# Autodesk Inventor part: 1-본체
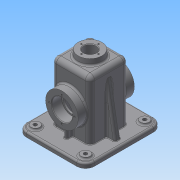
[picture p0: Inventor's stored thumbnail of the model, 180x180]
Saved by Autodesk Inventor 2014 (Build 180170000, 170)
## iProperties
Created: 2015-12
Part Number: 1-본체
Material: Generic
Document SubType Name: Modeling
Designer: Administrator
Density: 1 g/cm^3
Appearance: Default
Author: Administrator
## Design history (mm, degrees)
sketch "스케치1"
  geometry: L1 (-32.5, 32.5)-(32.5, 32.5); L2 (32.5, 32.5)-(32.5, -32.5); L3 (32.5, -32.5)-(-32.5, -32.5); L4 (-32.5, -32.5)-(-32.5, 32.5); L5 (-32.5, 32.5)-(32.5, -32.5); L6 (32.5, 32.5)-(-32.5, -32.5); 1 further point
  constraints: 12 end point, 2 midpoint, 2 parallel, 1 horizontal, 1 perpendicular
  dimensions: "d0" = 65 distance of L2.end L3.end; "d1" = 65 distance of L1.end L2.end
extrude "돌출1" new body sketch "스케치1" distance "d2" = 55; taper "d4" = 0 deg; dims "d3" = 55, "d5" = 0
feature "쉘1" dims "d6" = 5
node "작업 평면1"
sketch "스케치2"
  geometry: C1 r 20 at (0, 0); 1 further point
  constraints: 1 centre point, 1 coincident
  dimensions: "d8" = 40 diameter of C1
extrude "돌출2" join sketch "스케치2" stored distance "d9" = 55; taper "d10" = 5 deg
sketch "스케치3"
  geometry: C1 r 20 at (0, 0) reference; C2 r 10.5 at (0, 0)
  constraints: 1 centre point, 1 coincident
  dimensions: "d11" = 21 diameter of C2
extrude "돌출3" cut sketch "스케치3" stored distance "d12" = 55; taper "d13" = 0 deg
sketch "스케치4" dims "d14" = 29
  geometry: C1 r 20 at (0, 0) reference; 2 further points
  constraints: 1 coincident, 1 vertical alignment, 2 other
hole "구멍1" sketch "스케치4" at (0, 14.5) diameter "d15" = 2.459; stored, may be unused: countersink angle "d19" = 90 deg, drill point angle "d21" = 118 deg; dims "d16" = 7, "d17" = 4, "d18" = 2, "d20" = 9
sketch "스케치5"
  geometry: C1 r 27.5 at (32.5, -55); 1 further point
  constraints: 1 centre point, 1 coincident
  dimensions: "d25" = 55 diameter of C1
extrude "돌출4" join sketch "스케치5" distance "d26" = 15; taper "d27" = 0 deg
sketch "스케치6"
  geometry: C1 r 27.5 at (0, 0) reference; C2 r 17.5 at (0, 0)
  constraints: 1 centre point, 1 coincident
  dimensions: "d28" = 35 diameter of C2
extrude "돌출5" cut sketch "스케치6" distance "d29" = 17; taper "d30" = 0 deg
sketch "스케치7"
  geometry: C1 r 17.5 at (0, 0) reference; C2 r 15 at (0, 0)
  constraints: 1 centre point, 1 coincident
  dimensions: "d31" = 30 diameter of C2
extrude "돌출6" cut sketch "스케치7" distance "d32" = 3; taper "d33" = 0 deg
sketch "스케치8" dims "d34" = 42
  geometry: C1 r 27.5 at (0, 0) reference; 2 further points
  constraints: 1 coincident, 1 vertical alignment, 2 other
hole "구멍2" sketch "스케치8" at (0, 21) diameter "d35" = 3.242; stored, may be unused: countersink angle "d39" = 90 deg, drill point angle "d41" = 118 deg; dims "d36" = 8, "d37" = 4, "d38" = 2, "d40" = 10
sketch "스케치9"
  geometry: L1 (32.5, 32.5)-(-32.5, 32.5) reference; L2 (-32.5, 32.5)-(-32.5, -32.5) reference; L3 (-32.5, -32.5)-(32.5, -32.5) reference; L4 (32.5, -32.5)-(32.5, 32.5) reference; L5 (-42.5, -60)-(42.5, -60); L6 (52.5, -50)-(52.5, 50); L7 (42.5, 60)-(-42.5, 60); L8 (-52.5, 50)-(-52.5, -50); L9 (-52.5, -60)-(52.5, 60); L10 (52.5, -60)-(-52.5, 60); A1 r 10 centre (-42.5, -50) between (-52.5, -50) and (-42.5, -60); A2 r 10 centre (42.5, -50) between (42.5, -60) and (52.5, -50); A3 r 10 centre (42.5, 50) between (52.5, 50) and (42.5, 60); A4 r 10 centre (-42.5, 50) between (-42.5, 60) and (-52.5, 50); 1 further point
  constraints: 12 end point, 8 point on circle, 8 point on line, 8 tangent, 4 centre point, 3 equal radius, 2 midpoint, 2 parallel, 1 horizontal, 1 perpendicular
  dimensions: "d45" = 105 distance of L10.end L9.end; "d46" = 120 distance of L9.end L10.start; "d47" = 10 radius of A1
extrude "돌출7" join sketch "스케치9" distance "d48" = 2; taper "d49" = 0 deg
sketch "스케치10"
  geometry: L1 (32.5, -32.5)-(32.5, 32.5) reference; L2 (-32.5, -32.5)-(32.5, -32.5) reference; L3 (-32.5, 32.5)-(-32.5, -32.5) reference; L4 (32.5, 32.5)-(-32.5, 32.5) reference; L5 (42.5, -65)-(-42.5, -65); L6 (-57.5, -50)-(-57.5, 50); L7 (-42.5, 65)-(42.5, 65); L8 (57.5, 50)-(57.5, -50); L9 (57.5, -65)-(-57.5, 65); L10 (-57.5, -65)-(57.5, 65); A1 r 15 centre (42.5, -50) between (42.5, -65) and (57.5, -50); A2 r 15 centre (-42.5, -50) between (-57.5, -50) and (-42.5, -65); A3 r 15 centre (-42.5, 50) between (-42.5, 65) and (-57.5, 50); A4 r 15 centre (42.5, 50) between (57.5, 50) and (42.5, 65); 1 further point
  constraints: 12 end point, 8 point on circle, 8 point on line, 8 tangent, 4 centre point, 2 midpoint, 2 parallel, 1 horizontal, 1 perpendicular
  dimensions: "d50" = 115 distance of L9.end L10.end; "d51" = 130 distance of L10.start L9.end; "d52" = 15 radius of A1; "d53" = 15 radius of A2; "d54" = 15 radius of A3; "d55" = 15 radius of A4
extrude "돌출8" join sketch "스케치10" distance "d56" = 8; taper "d57" = 0 deg
sketch "스케치11"
  geometry: C1 r 3 at (-42.5, -50); C2 r 3 at (-42.5, 50); C3 r 3 at (42.5, 50); C4 r 3 at (42.5, -50); A1 r 10 centre (42.5, -50) between (42.5, -60) and (52.5, -50) reference; A2 r 10 centre (42.5, 50) between (52.5, 50) and (42.5, 60) reference; A3 r 10 centre (-42.5, 50) between (-42.5, 60) and (-52.5, 50) reference; A4 r 10 centre (-42.5, -50) between (-52.5, -50) and (-42.5, -60) reference; 1 further point
  constraints: 4 centre point, 4 coincident
  dimensions: "d58" = 6 diameter of C1; "d59" = 6 diameter of C2; "d60" = 6 diameter of C3; "d61" = 6 diameter of C4
extrude "돌출9" cut sketch "스케치11" distance "d62" = 10; taper "d63" = 0 deg
sketch "스케치12"
  geometry: C1 r 3 at (-42.5, 50) reference; C2 r 3 at (42.5, -50) reference; C3 r 3 at (42.5, 50) reference; C4 r 3 at (-42.5, -50) reference; C5 r 7.5 at (-42.5, -50); C6 r 7.5 at (-42.5, 50); C7 r 7.5 at (42.5, 50); C8 r 7.5 at (42.5, -50); A1 r 15 centre (42.5, -50) between (42.5, -65) and (57.5, -50) reference; A2 r 15 centre (42.5, 50) between (57.5, 50) and (42.5, 65) reference; A3 r 15 centre (-42.5, 50) between (-42.5, 65) and (-57.5, 50) reference; A4 r 15 centre (-42.5, -50) between (-57.5, -50) and (-42.5, -65) reference; 1 further point
  constraints: 4 centre point, 3 concentric, 1 coincident
  dimensions: "d64" = 15 diameter of C5; "d65" = 15 diameter of C6; "d66" = 15 diameter of C7; "d67" = 15 diameter of C8
extrude "돌출10" join sketch "스케치12" distance "d68" = 3; taper "d69" = 0 deg
sketch "스케치14"
  geometry: L1 (-27.5, 50)-(-27.5, -55) reference; L2 (-27.5, -55)-(-52.5, -55) reference; L3 (-52.5, -55)-(-52.5, -53) reference; L4 (-52.5, -53)-(-57.5, -53) reference; L5 (-57.5, -53)-(-57.5, -45) reference; L6 (-57.5, -45)-(-32.5, -45) reference; L7 (-32.5, -45)-(-32.5, 55) reference; L8 (-32.5, 55)-(-20.875, 55) reference; L9 (-20.875, 55)-(-20, 65) reference; L10 (-20, 65)-(-15.73, 65) reference; L11 (-15.73, 65)-(-15.73, 56) reference; L12 (-15.73, 56)-(-14.5, 55.261) reference; L13 (-14.5, 55.261)-(-13.27, 56) reference; L14 (-13.27, 56)-(-13.27, 65) reference; L15 (-13.27, 65)-(-10.5, 65) reference; L16 (-10.5, 65)-(-10.5, 50) reference; L17 (-10.5, 50)-(-27.5, 50) reference; L18 (27.5, -55)-(27.5, 50) reference; L19 (27.5, 50)-(10.5, 50) reference; L20 (10.5, 50)-(10.5, 65) reference; L21 (10.5, 65)-(13.27, 65) reference; L22 (13.27, 65)-(13.27, 56) reference; L23 (13.27, 56)-(14.5, 55.261) reference; L24 (14.5, 55.261)-(15.73, 56) reference; L25 (15.73, 56)-(15.73, 65) reference; L26 (15.73, 65)-(20, 65) reference; L27 (20, 65)-(20.875, 55) reference; L28 (20.875, 55)-(32.5, 55) reference; L29 (32.5, 55)-(32.5, -45) reference; L30 (32.5, -45)-(57.5, -45) reference; L31 (57.5, -45)-(57.5, -53) reference; L32 (57.5, -53)-(52.5, -53) reference; L33 (52.5, -53)-(52.5, -55) reference; L34 (52.5, -55)-(27.5, -55) reference; L35 (47.5, -45)-(32.5, 40.069); L36 (47.5, -45)-(147.172, -45); 1 further point
  constraints: 4 end point, 2 point on line, 1 horizontal
  dimensions: "d70" = 100 deg angle of L36 L35; "d71" = 10 distance of L30.end L35.start
feature "리브1" sketch "스케치14" dims "d72" = 1, "d73" = 10, "d74" = 0, "d75" = 0, "d76" = 1, "d77" = 1
sketch "스케치15"
  geometry: L1 (42.5, -45)-(42.5, -27.5); L2 (50, -55)-(-50, -55) reference; L3 (47.5, -27.5)-(32.5, -27.5) reference; L4 (-50, -45)-(50, -45) reference; L5 (27.5, 50)-(27.5, -55) reference; 1 further point
  constraints: 2 end point, 2 point on line
  dimensions: "d79" = 15 distance between parallel lines of L5 L1
feature "리브2" sketch "스케치15" dims "d80" = 1, "d81" = 6, "d82" = 0, "d83" = 0, "d84" = 1, "d85" = 1
sketch "스케치16"
  geometry: L1 (65, 0)-(65, 100) reference; L2 (52.5, -10)-(12.5, -10) reference; 1 further point
  constraints: 1 other
  dimensions: "d86" = 26 distance from line of point (32.5, 16) L2; "d87" = 32.5 distance from line of L1 point (32.5, 16)
feature "엠보싱1" sketch "스케치16" dims "d88" = 0.5, "d89" = 0
chamfer "모따기1" distance "d90" = 1; stored, may be unused: second distance "d91" = 2, angle "d92" = 45 deg
fillet "모깎기1" dims "d93" = 0.3
fillet "모깎기2" dims "d94" = 8
fillet "모깎기3" dims "d95" = 8
fillet "모깎기4" dims "d96" = 3
fillet "모깎기5" dims "d97" = 3
fillet "모깎기7" dims "d99" = 3
fillet "모깎기8" dims "d100" = 3
fillet "모깎기9" dims "d101" = 3
fillet "모깎기10" dims "d102" = 3
fillet "모깎기11" dims "d103" = 3
fillet "모깎기12" dims "d104" = 1
node "솔리드1"
pattern_circular "원형 패턴1" dims angle "d23" = 360 deg
pattern_circular "원형 패턴2" dims angle "d43" = 360 deg
mirror "대칭1"
mirror "대칭2"
mirror "대칭3"
node "절단 모서리 투영1"
other parameters: "d7" = 65
